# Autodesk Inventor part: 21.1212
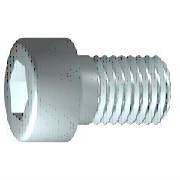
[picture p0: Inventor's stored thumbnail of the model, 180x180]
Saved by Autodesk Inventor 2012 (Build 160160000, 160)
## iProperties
Created: 2006-02
Part Number: 21.1212
Material: Steel, Mild
Description: M8 X 50 SHCS
Document SubType Name: Modeling
Standard: DIN 7984
Designer: Andy Moles
Standards Organization: DIN
Language: en-US
Size Designation: M8 x 50
Categories: <MemberInstance><Categories><Category DisplayName="Fasteners" InternalName="e4da775c-781d-43d5-af7c-5136215cf5a6" Mnemonic="FSTN"><Category DisplayName="Bolts"
Density: 7.86 g/cm^3
Mass: 24.1156 g
Surface Area: 17.7165 cm^2
Volume: 3.06815 cm^3
Author: Andy Moles
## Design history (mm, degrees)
body "Solid1"
workplane "Work Plane1"
revolve "Body" stored, may be unused: angle "d10" = 90 deg
sketch "Sketch2"
  geometry: L1 (0, -7.8)-(0, 10.4) reference; L2 (-7.8, 0)-(10.4, 0) reference; L3 (2.887, 0)-(1.443, -2.5); L4 (1.443, -2.5)-(-1.443, -2.5); L5 (-1.443, -2.5)-(-2.887, 0); L6 (-2.887, 0)-(-1.443, 2.5); L7 (-1.443, 2.5)-(1.443, 2.5); L8 (1.443, 2.5)-(2.887, 0); 2 further points
  constraints: 12 end point, 1 coincident, 1 horizontal alignment, 1 point on line, 12 other
extrude "Slot" join sketch "Sketch2" stored distance "d11" = 10; taper "d12" = 0 deg
fillet "Fillet1" dims "d17" = 0.8 (= RR)
feature "Thread" dims "d13" = 22 (= GEL), "d14" = 0
chamfer "Chamfer1" distance "d15" = 0.76681 (= -0.5 x SPD + 0.5 x GD); stored, may be unused: second distance "d16" = 0.76681 (= GUL), angle "d27" = 45 deg
sketch "Sketch1"
  geometry: L1 (0.467, 0)-(50, 0); L2 (50, 0)-(50, 4); L3 (50, 4)-(28, 4); L4 (28, 4)-(27.233, 4); L5 (27.233, 4)-(0, 4); L6 (0, 4)-(0, 6.5); L7 (0, 6.5)-(-5, 6.5); L8 (-5, 6.5)-(-5, 2.887); L9 (-5, 2.887)-(-1.2, 2.887); L10 (-1.2, 2.887)-(0.467, 0); L11 (-10.5, 0)-(66.5, 0) reference; L12 (0, -0.65)-(0, 8.45) reference; L13 (28, 4)-(0, 4)
  constraints: 22 end point, 6 parallel, 2 collinear, 2 perpendicular, 1 horizontal, 1 point on line
  dimensions: "d1" = 22 distance from line of L3.end L2 (= GEL); "d2" = 0.76691 distance of L4.end L3.end (computed from GAL); "d3" = 5 distance between parallel lines of L8 L6 (= KOH); "d4" = 3.8 distance of L8.end L9.end (= INTI); "d5" = 60 deg angle of L10 L1; "d6" = 8 diameter of L3 L1 (= GD); "d7" = 8 diameter of L5 L1 (= BDM); "d8" = 5.7735 diameter of L9 L1 (= 1.1547 x SW); "d9" = 13 diameter of L7 L1 (= KOD); "d26" = 50 distance between parallel lines of L12 L2 (= NLG)
other parameters: "GD" = 8 (= NND) [user parameter; used in 2 equation terms], "NLG" = 50 [user parameter; used in 1 equation term], "GEL" = 22 [user parameter; used in 2 equation terms], "KOD" = 13 [user parameter; used in 1 equation term], "KOH" = 5 [user parameter; used in 1 equation term], "INTI" = 3.8 [user parameter; used in 1 equation term], "GAL" = 0.76681 (= 0.61345 x PTC) [user parameter; used in 1 equation term], "GUL" = 0.76681 (= 0.61345 x PTC) [user parameter; used in 1 equation term], "BDM" = 8 (= NND) [user parameter; used in 1 equation term], "SW" = 5 [user parameter; used in 2 equation terms], "RR" = 0.8 [user parameter; used in 1 equation term], "SPD" = 6.46637 (= NND - 1.2269 x PTC) [user parameter; used in 1 equation term], "d19" = 0, "d28" = 0, "d29" = 0, "TOA" = 30 deg [user parameter], "GD1" = 6.46637 (= THREADDIA - 1.2269 x PTC) [user parameter], "THREADDIA" = 8 [user parameter; used in 1 equation term], "FAWI" = 45 deg [user parameter], "ANG" = 120 deg [user parameter], "TPU" = 8 (computed from PTC) [user parameter], "PTC" = 1.25 [user parameter; used in 5 equation terms], "NND" = 8 [user parameter; used in 3 equation terms], "E0" = 5.775 (= 1.155 x SW) [user parameter]
